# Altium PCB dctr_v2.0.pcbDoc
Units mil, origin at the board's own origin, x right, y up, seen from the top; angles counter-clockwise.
Board outline 7322.83 x 1023.62 mil, 2 copper layers (Top Layer, Bottom Layer); 19 components, 20 nets, 83 pads, 18 vias.
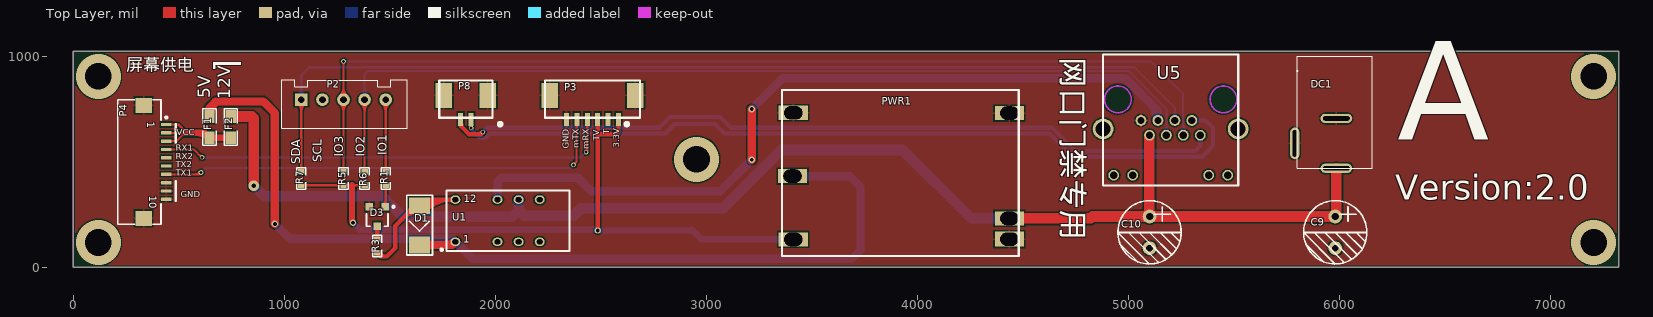
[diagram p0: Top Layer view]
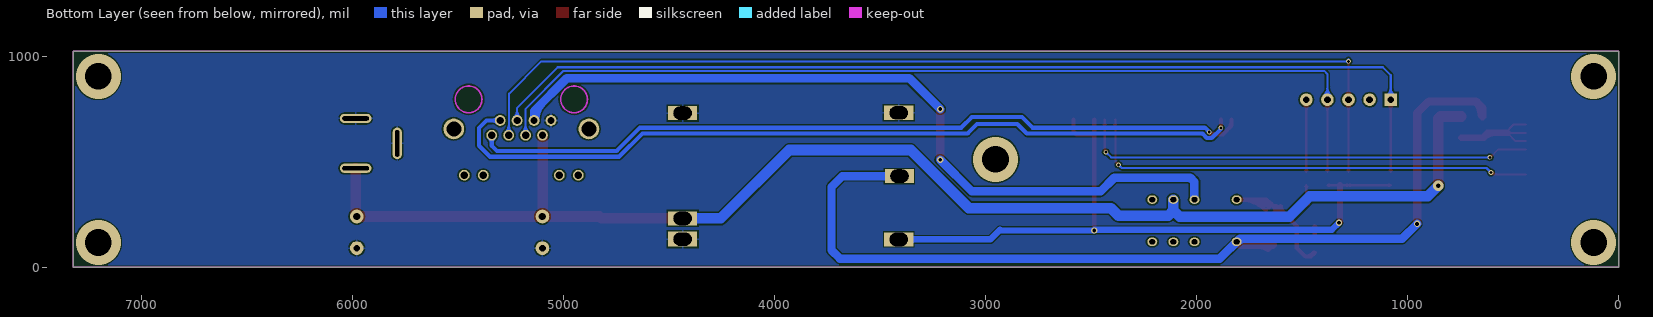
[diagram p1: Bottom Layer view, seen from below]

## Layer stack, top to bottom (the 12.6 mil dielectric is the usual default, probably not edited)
Top Layer: signal copper 1.4
Dielectric: core 12.6, FR-4, Dk 4.8
Bottom Layer: signal copper 1.4

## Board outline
0,0 7322.83,0 7322.83,1023.62 0,1023.62

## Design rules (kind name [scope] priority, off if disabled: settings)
Clearance [All] p1: gap=7
ComponentClearance [All] p1: gap=0 collisioncheckmode=3 verticalgap=0 showdistances=FALSE
HoleSize [All] p1: absolutevalues=TRUE maxlimit=1000 minlimit=1 maxpercent=80.000 minpercent=20.000
HoleToHoleClearance [All] p1: gap=7 allowstackedmicrovias=TRUE
MinimumSolderMaskSliver [All] p1: minsoldermaskwidth=0
PolygonConnect [All] p1: connectstyle=Relief reliefconductorwidth=10 reliefentries=4 polygonreliefangle="90 Angle"
RoomDefinition IO [InComponentClass('IO')] p1: confinementstyle=ConfineIn formatcopy=TRUE lockcomponents=FALSE outline -12707.68,-5560.81 -10707.68,-5560.81 -10707.68,-4560.81 -12707.68,-4560.81
RoutingVias [All] p1: holewidth=14 width=22 viastyle="Through Hole" minholewidth=14 minwidth=22 maxholewidth=280 maxwidth=500
SilkToSilkClearance [All] p1: silktosilkclearance=0
SilkscreenOverComponentPads [All] p1: minsilkscreentomaskgap=0
SolderMaskExpansion [All] p1: expansion=4
TestPointUsage [All] p1: valid=0 allowmultiple=FALSE
Testpoint [All] p1: side=15 testpointundercomponent=TRUE minsize=40 maxsize=100 preferedsize=60 minholesize=0 maxholesize=40 preferedholesize=32 testpointgrid=1 style=1023 order=0-112345678
Width [All] p1: maxlimit=100 minlimit=7 preferedwidth=7
18 further rules are at their usual default settings.

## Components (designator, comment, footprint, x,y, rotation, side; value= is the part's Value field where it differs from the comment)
C9 "220uF" RB.15/.3 5980,241.26 r90 top
C10 "220uF" RB.15/.3 5100,241.26 r90 top
D1 "D-S" DO-214AC(SMA) 1580,341.26 r270 top
D3 "AO3400A" SOT23A 1440,241.26 r180 top
DC1 "DC" DC005 5800,1001.26 r270 top
F1 "FUSE" 0805F 645,665.12 r270 top
F2 "FUSE" 0805F 745,665.12 r270 top
P2 "Header 5" XH2.54-5 1280,794.8 r0 top
P3 "Header 8" FPC/1.25T-6P 2460,701.26 r180 top
P4 "Header 12" FFC/SM1.0-2H10 440,500 r270 top
P8 "Header 4" FPC/1.25T-2P 1860,701.26 r180 top
PWR1 "PWR-1" PWR-1 4480,841.26 r180 top locked
R1 "10K" 0603R 1480,421.26 r90 top
R3 "10K" 0603R 1440,101.26 r90 top
R5 "10K" 0603R 1280,421.26 r270 top
R6 "10K" 0603R 1380,421.26 r270 top
R7 "10K" 0603R 1080,421.26 r270 top
U1 "JDQ(G6S-2)" JDQ-G6S-2 2060,221.26 r0 top
U5 "RJ45-DTE" RJ45-2 5200,661.26 r0 top

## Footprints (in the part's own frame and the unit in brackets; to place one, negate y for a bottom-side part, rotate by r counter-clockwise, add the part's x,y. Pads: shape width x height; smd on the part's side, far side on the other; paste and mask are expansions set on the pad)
0603R [mil]
  rect 25x30 smd: 1(-32,0) 2(32,0)
  silkscreen extent -51,-22 51,22
0805F [mil]
  rect 60x49.21 smd: 1(-50,0) 2(50,0)
  silkscreen extent -87,-31 86,31
DC005 [mm] "9*13.5*10( 外径5.5mm 内径2.1mm)"
  oval 1.1x3.8 hole 0.5 slot 3.2 at 90 deg: 1(13.5,4.7) 2(7.5,4.7)
  oval 3.8x1.1 hole 0.5 slot 3.2 at 0 deg: 3(10.5,-0.3)
  silkscreen extent 0,0 13.5,9
DO-214AC(SMA) [mm]
  rect 2x2.5 smd: A(1.27,1.524) K(5.969,1.524)
  silkscreen extent 0,0 7.19,3.1
FFC/SM1.0-2H10 [mm] "Connector; FH12 Series; 6 Position; 1.0mm Spaced Bottom Eccentric Contact"
  rect 0.4x1.25 smd: 1(-4.5,0) 2(-3.5,0) 3(-2.5,0) 4(-1.5,0) 5(-0.5,0) 6(0.5,0) 7(1.5,0) 8(2.5,0) 9(3.5,0) 10(4.5,0)
  rect 1.8x2 smd: 11(-6.8,-2.725) 12(6.8,-2.725)
  silkscreen extent -7.5,-5.82 7.5,0.13
FPC/1.25T-2P [mm]
  rect 0.6x1.6 smd: 1(-0.625,0) 2(0.625,0)
  rect 2x3 smd: 3(-2.65,-2.9) 4(2.65,-2.9)
  silkscreen extent -4.28,-4.7 3.2,0.71
FPC/1.25T-6P [mm]
  rect 0.6x1.6 smd: 1(-3.125,0) 2(-1.875,0) 3(-0.625,0) 4(0.625,0) 5(1.875,0) 6(3.125,0)
  rect 2x3 smd: 7(-5.15,-2.9) 8(5.15,-2.9)
  silkscreen extent -5.7,-4.7 5.7,0.71
JDQ-G6S-2 [mm] "继电器（G6S-2） 5VDC"
  oval 1.2x1 hole 0.6 slot 0.7 at 0 deg: 1(-6.35,-2.54) 3(-1.27,-2.54) 4(1.27,-2.54) 5(3.81,-2.54) 8(3.81,2.54) 9(1.27,2.54) 10(-1.27,2.54) 12(-6.35,2.54)
  silkscreen extent -8.14,-3.65 7.4,3.65
PWR-1 [mm]
  rect 3.5x1.8 hole 1.6 slot 2.2 at 0 deg: 1(1.125,17.975)
  rect 3.5x1.7 hole 1.6 slot 2.2 at 0 deg: 2(1.125,15.475) 3(1.125,2.8) 4(27.141,2.76) 5(27.225,10.38) 6(27.141,18)
  silkscreen extent 0,0 28.5,20
RB.15/.3 [mil] "8x11x3.5mm"
  round 65 hole 35: 1(0,0)
  round 65 hole 32: 2(-150,0)
  silkscreen extent -225,-150 75,150
RJ45-2 [mm] "FC601-56S-LED"
  round 2.5 hole 1.8: 0(-8.13,-0.13) 0(8.13,-0.13)
  round 1.3 hole 0.89: 1(-3.57,0.89) 2(-2.55,-0.89) 3(-1.53,0.89) 4(-0.51,-0.89) 5(0.51,0.89) 6(1.53,-0.89) 7(2.55,0.89) 8(3.57,-0.89) 9(-6.86,-5.7) 10(-4.57,-5.7) 11(4.57,-5.7) 12(6.86,-5.7)
  Keep-Out Layer circle w0.203: c6.35,3.43 r1.61
  Keep-Out Layer circle w0.203: c-6.35,3.43 r1.61
  silkscreen extent -8.13,-6.92 8.13,8.83
SOT23A [mm] "SOT-23; 3 Leads; Body 3.0 x 2.5 mm, inc. leads (LxW max)"
  rect 0.9x0.95 smd: 1(-0.95,-1.175) 2(0.95,-1.175) 3(0,1.175)
  silkscreen extent -2.07,-1.3 1.3,1.18
XH2.54-5 [mil]
  rect 60x60 hole 32: 1(-200,0)
  round 60 hole 32: 2(-100,0) 3(0,0) 4(100,0) 5(200,0)
  silkscreen extent -292,-136 301,94

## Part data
C9 C10: library part CAP-E, "电解电容"
D1: "肖特基二极管"
D3: library part MOS-N, "NMOS"
DC1: library part DC00X, "圆形电源接口"
F1 F2: "CR-1812-050A60V"
P2: "Header, 5-Pin"
P3: "Header, 8-Pin"
P4: "Header, 12-Pin"
P8: "Header, 4-Pin"
R1 R3 R5 R6 R7: library part RES, "普通电阻"
U1: "继电器（G6S-2 5VDC）"
U5: "设备"

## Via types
v1: diameter 22, hole 14, Top Layer to Bottom Layer, tented both sides, 7 vias
v2: diameter 212.6, hole 125.98, Top Layer to Bottom Layer, 5 vias
v3: diameter 30, hole 18, Top Layer to Bottom Layer, tented both sides, 3 vias
v4: diameter 30, hole 18, Top Layer to Bottom Layer, 2 vias
v5: diameter 50, hole 22, Top Layer to Bottom Layer, tented both sides, 1 vias

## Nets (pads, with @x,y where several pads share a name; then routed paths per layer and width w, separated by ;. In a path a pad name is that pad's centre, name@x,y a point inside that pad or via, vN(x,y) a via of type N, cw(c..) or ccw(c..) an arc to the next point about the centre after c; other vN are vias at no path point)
BTN: P2.3 R5.1 U5.6 | length 5258.9
  Top Layer w10: P2.3@1262.32,777.12 cw(c1219.64,734.44) 1280,734.44 cw(c1340.36,734.44) P2.3@1297.68,777.12 ; P2.3@1262.32,812.48 ccw(c1219.64,855.15) 1280,855.15 ccw(c1340.36,855.15) P2.3@1297.68,812.48 ; P2.3@1269.39,784.19 cw(c1243.79,758.59) 1280,758.59 cw(c1316.21,758.59) P2.3@1290.61,784.19 ; P2.3@1269.39,805.41 ccw(c1243.79,831.01) 1280,831.01 ccw(c1316.21,831.01) P2.3@1290.61,805.41 ; R5.1@1274.7,458.56 ccw(c1261.89,471.37) 1280,471.37 ccw(c1298.11,471.37) R5.1@1285.3,458.56 ; v1@1275.76,972.02 cw(c1265.51,961.77) 1280,961.77 cw(c1294.49,961.77) v1@1284.24,972.02 ; R5.1 P2.3 v1(1280,976.26)
  Bottom Layer w10: v1(1280,976.26) 1280,986.26 1290,976.26 5105,976.26 5257.67,823.59 5257.67,628.79 U5.6 ; v1@1284.24,972.02 cw(c1294.49,961.77) 1294.49,976.26 cw(c1294.49,990.75) v1@1284.24,980.5 ; U5.6@5245.68,640.78 ccw(c5216.72,669.73) 5257.67,669.73 ; 5257.67,657.99 ccw(c5292,657.99) U5.6@5267.72,633.71 ; 5257.67,682.13 ccw(c5316.14,682.13) U5.6@5274.8,640.78
D3V3: P3.1 P3.3 PWR1.6 R5.2 R6.2 R7.2 | length 3464.7
  Top Layer w10: R7.2 R5.2 1320,389.26 R6.2 ; R7.2@1087.8,383.96 cw(c1100.61,371.15) 1100.61,389.26 cw(c1100.61,407.37) R7.2@1087.8,394.56 ; R5.2@1272.2,383.96 ccw(c1259.39,371.15) 1259.39,389.26 ccw(c1259.39,407.37) R5.2@1272.2,394.56 ; R5.2@1287.8,383.96 cw(c1300.61,371.15) 1300.61,389.26 cw(c1300.61,407.37) R5.2@1287.8,394.56 ; R6.2@1372.2,383.96 ccw(c1359.39,371.15) 1359.39,389.26 ccw(c1359.39,407.37) R6.2@1372.2,394.56
  Top Layer w20: v4@2484.61,175.39 2484.61,631.26 ; P3.3 2484.61,631.26 ; P3.1 2583.03,644.29 2570,631.26 2484.61,631.26
  Top Layer w30: v3@1320,216.26 1320,389.26
  Bottom Layer w20: 2928.83,175 2931.47,177.64
  Bottom Layer w30: v3(1325,211.26) 1358.62,177.64 2485,177.64 2487.64,175 2928.83,175 ; 2931.47,177.64 2976.51,132.6 PWR1.6 ; PWR1.6@3362.98,119.54 ccw(c3331.46,88.02) 3331.46,132.6 ccw(c3331.46,177.18) PWR1.6@3362.98,145.65
  other v4: 2485,175
D5V: D1.K F1.1 PWR1.5 U1.1 | length 4814
  Top Layer w40: F1.1 645,756.26 675,786.26 ; F1.1@649.6,720.73 cw(c736.53,724.72) 675,786.26 ; v3(955,206.26) 955,731.26 900,786.26 675,786.26 ; D1.K 1795,106.26 U1.1 ; D1.K@1663.54,92.56 cw(c1696.61,59.5) 1696.61,106.26 cw(c1696.61,153.02) D1.K@1663.54,119.96 ; 1770.61,106.26 ccw(c1770.61,156.71) U1.1@1806.29,121.04
  Bottom Layer w40: v3(955,206.26) 1025.62,135.64 1795.62,135.64 1890,41.26 3690,41.26 3730,81.26 3730,381.26 3678.66,432.6 PWR1.5 ; 1772.11,135.64 cw(c1772.11,87.31) U1.1@1806.29,121.48
D12V: C9.1 C10.1 DC1.1 F2.1 PWR1.2 U1.9 U5.2 | length 6575.5
  Top Layer w50: F2.1 846.14,715.12 855,706.26 v5(855,386.26) ; PWR1.2 4820.75,232.01 4830,241.26 C10.1 C9.1 5985.04,246.3 DC1.1 ; C10.1@5099.61,241.65 U5.2
  Bottom Layer w50: v5(855,386.26) 905,336.26 1463.74,336.26 1560,240 2080,240 2110,270 ; U1.9 2110,270 ; PWR1.2 4254.25,232.01 3930,556.26 3355,556.26 3080,281.26 2406.26,281.26 2370,245 2135,245 2110,270
FEED1: P2.4 R6.1 U5.4 | length 4878.7
  Top Layer w10: P2.4@1362.32,777.12 cw(c1319.64,734.44) 1380,734.44 cw(c1440.36,734.44) P2.4@1397.68,777.12 ; P2.4@1369.39,784.19 cw(c1343.79,758.59) 1380,758.59 cw(c1416.21,758.59) P2.4@1390.61,784.19 ; R6.1@1374.7,458.56 ccw(c1361.89,471.37) 1380,471.37 ccw(c1398.11,471.37) R6.1@1385.3,458.56 ; R6.1 P2.4
  Bottom Layer w10: P2.4@1362.32,812.48 ccw(c1319.64,855.15) 1380,855.15 ccw(c1440.36,855.15) P2.4@1397.68,812.48 ; P2.4@1369.39,805.41 ccw(c1343.79,831.01) 1380,831.01 ccw(c1416.21,831.01) P2.4@1390.61,805.41 ; P2.4 1380,916.26 1395,931.26 5000,931.26 5179.92,751.34 U5.4 ; U5.4@5165.36,640.78 ccw(c5130.21,675.93) 5179.92,675.93 ccw(c5229.63,675.93) U5.4@5194.48,640.78
FEED2: P2.1 R7.1 U5.5 | length 5162.8
  Top Layer w10: P2.1@1062.32,777.12 cw(c1019.64,734.44) 1080,734.44 cw(c1140.36,734.44) P2.1@1097.68,777.12 ; P2.1@1069.39,784.19 cw(c1043.79,758.59) 1080,758.59 cw(c1116.21,758.59) P2.1@1090.61,784.19 ; R7.1@1074.7,458.56 ccw(c1061.89,471.37) 1080,471.37 ccw(c1098.11,471.37) R7.1@1085.3,458.56 ; R7.1 P2.1
  Bottom Layer w10: P2.1@1062.32,812.48 ccw(c1019.64,855.15) 1080,855.15 ccw(c1140.36,855.15) P2.1@1097.68,812.48 ; P2.1@1069.39,805.41 ccw(c1043.79,831.01) 1080,831.01 ccw(c1116.21,831.01) P2.1@1090.61,805.41 ; P2.1 1080,911.26 1117,948.26 5028,948.26 5220.08,756.18 U5.5 ; U5.5@5205.52,710.86 ccw(c5170.37,746.01) 5220.08,746.01 ccw(c5269.79,746.01) U5.5@5234.64,710.86
GND: C9.2 C10.2 D3.2 DC1.2 DC1.3 P3.6 P3.7 P3.8 P4.8 P4.9 P4.10 P4.11 P4.12 P8.3 P8.4 PWR1.1 PWR1.3 PWR1.4 U5.1
IO1: P2.5 R1.2 | length 521.7
  Top Layer w10: P2.5@1462.32,777.12 cw(c1419.64,734.44) 1480,734.44 cw(c1540.36,734.44) P2.5@1497.68,777.12 ; P2.5@1469.39,784.19 cw(c1443.79,758.59) 1480,758.59 cw(c1516.21,758.59) P2.5@1490.61,784.19 ; R1.2@1474.7,458.56 ccw(c1461.89,471.37) 1480,471.37 ccw(c1498.11,471.37) R1.2@1485.3,458.56 ; R1.2 P2.5
LOCK_V+: U1.10 U5.3 | length 3816.2
  Top Layer w40: v4(3215,510) v3(3215,750)
  Bottom Layer w40: U1.10 2010,405 2030,425 2390,425 2455,360 3065,360 v4(3215,510) ; v3(3215,750) 3361.26,896.26 4984.67,896.26 5139.76,741.17 U5.3 ; 5098.49,782.44 cw(c5012.35,696.3) U5.3@5134.17,696.3
NetD1_A: D1.A R3.1 U1.12 | length 1077.1
  Top Layer w20: R3.1 1458,51.26 1485,51.26 ; R3.1@1444.46,70.82 ccw(c1485,103.06) 1485,51.26 ; 1562.68,233.94 cw(c1630.16,166.46) D1.A@1630.16,261.89 ; 1587.2,258.46 ccw(c1554.4,291.26) D1.A@1600.79,291.26 ; D1.A@1596.82,268.08 cw(c1630.16,234.75) D1.A@1630.16,281.89 ; D1.A@1642.33,298.78 cw(c1696.61,244.5) 1696.61,321.26 ; D1.A@1656.47,284.63 cw(c1744.89,196.21) 1744.89,321.26 ; D1.A@1670.61,270.49 cw(c1793.17,147.93) U1.12@1793.17,321.26 ; U1.12@1799.21,314.41 ccw(c1782.68,297.88) 1782.68,321.26 ccw(c1782.68,344.64) U1.12@1799.21,328.11 ; U1.12 1670,321.26 D1.A 1620,291.26 1525,196.26 1525,91.26 1485,51.26
NetD3_1: D3.1 R1.1 | length 175.8
  Top Layer w10: D3.1@1468.41,297.5 ccw(c1440.43,325.48) 1480,325.48 ; R1.1@1474.7,383.96 cw(c1461.89,371.15) 1480,371.15 cw(c1498.11,371.15) R1.1@1485.3,383.96 ; D3.1@1480,290.12 R1.1 ; 1480,312.93 ccw(c1501.83,312.93) D3.1@1486.39,297.5
NetD3_3: D3.3 R3.2 | length 91
  Top Layer w20: D3.3@1434.54,188.56 cw(c1421.37,175.39) 1440,175.39 cw(c1458.63,175.39) D3.3@1445.46,188.56 ; R3.2 D3.3
NetF1_2: F1.2 F2.2 P4.1 P4.2 P4.3 | length 603.9
  Top Layer w10: P4.3 488.43,598.43 525.6,635.6 525.6,637.8 ; P4.2 525.6,637.8 ; P4.1 497.83,677.17 531.4,643.6 ; 537.2,637.8 531.4,643.6 ; 525.6,637.8 531.4,643.6
  Top Layer w30: 525.6,637.8 537.2,637.8 622.33,637.8 F1.2 F2.2 ; 580.09,637.8 cw(c580.09,555.6) F1.2@638.21,613.72
RX1: P3.4 P4.4 | length 2294
  Top Layer w10: P4.4 570.31,559.06 609.06,520.31 v1(610,521.26) ; 596.53,532.84 ccw(c610,546.31) v1@610,527.26 ; 601.09,528.28 cw(c594.08,521.26) v1@604,521.26 ; v1@2425.76,550.5 ccw(c2402.49,573.77) 2435.39,573.77 ; v1(2430,546.26) 2435.39,551.65 P3.4 ; P3.4@2430.58,676.76 cw(c2418.95,665.13) 2435.39,665.13 cw(c2451.84,665.13) P3.4@2440.21,676.76
  Bottom Layer w10: v1(610,521.26) 2405,521.26 v1(2430,546.26) ; v1@614.24,517.02 cw(c624.49,506.77) 624.49,521.26 cw(c624.49,535.75) v1@614.24,525.5 ; v1@2424,546.26 cw(c2409.51,546.26) 2419.76,536.02 cw(c2430,525.77) v1@2430,540.26
RX2: P4.5
SCL: P2.2
SPEAKERA: P8.1 U5.7 | length 3950.6
  Top Layer w20: P8.1 1884.61,661.46 1884.81,661.26 v1(1885,661.26)
  Bottom Layer w20: v1(1885,661.26) 1885,656.66 1928.4,613.26 1951.6,613.26 1968,629.66 1968,631.08 1972.03,635.11 2805.11,635.11 2850,680 3040,680 3084.89,635.11 4626.15,635.11 4737,524.26 5348,524.26 5400,576.26 5400,661.26 5364.96,696.3 U5.7 ; U5.7@5311.42,685.28 cw(c5338.03,658.66) 5338.03,696.3 cw(c5338.03,733.94) U5.7@5311.42,707.32
SPEAKERB: P8.2 U5.8 | length 3822.4
  Top Layer w20: P8.2@1835,700.87 1835,671.65 1875.39,631.26 1930,631.26 v1(1940,641.26) ; P8.2@1837.2,681.57 ccw(c1866.49,681.57) 1845.78,660.87 ; 1913.44,631.26 ccw(c1913.44,667.82) v1@1939.29,641.97
  Bottom Layer w20: v1(1940,641.26) 1960.85,662.11 2777.11,662.11 2827.11,712.11 3065,712.11 3115,662.11 4637.33,662.11 4748.18,551.26 5315,551.26 5340.55,576.81 U5.8 ; U5.8@5329.53,615.2 cw(c5302.91,588.58) 5340.55,588.58 cw(c5378.19,588.58) U5.8@5351.58,615.2
TX1: P3.5 P4.7 | length 2316.9
  Top Layer w10: P4.7 595.94,440.94 v1(605,450) ; 568.65,440.94 ccw(c568.65,486.35) v1@600.76,454.24 ; 592.8,440.94 ccw(c592.8,462.2) v1@607.83,447.17 ; v1(2370,486.26) 2385,501.26 2385,700.08 P3.5 ; v1@2370,492.26 ccw(c2370,506.75) 2380.24,496.5 ccw(c2390.49,486.26) v1@2376,486.26 ; P3.5@2381.36,676.76 cw(c2372.59,667.98) 2385,667.98 ; 2385,662.28 cw(c2405.48,662.28) P3.5@2391,676.76
  Bottom Layer w10: v1(605,450) 626.26,471.26 2355,471.26 v1(2370,486.26) ; v1@605,456 ccw(c605,470.49) 615.24,460.24 ccw(c625.49,450) v1@611,450 ; v1@2364,486.26 cw(c2349.51,486.26) 2359.76,476.02 cw(c2370,465.77) v1@2370,480.26
TX2: P4.6
pads on no net: P3.2 U1.3 U1.4 U1.5 U1.8 U5.0 U5.9 U5.10 U5.11 U5.12
copper on no net:
  other v2: 118.11,118.11 7204.72,118.11 2952.76,511.81 118.11,905.51 7204.72,905.51

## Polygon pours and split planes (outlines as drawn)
GND on Top Layer "Keep-Out Layer-No Net" (solid, remove dead copper): 0,1023.62 0,0 7322.83,0 7322.83,1023.62
GND on Bottom Layer "Keep-Out Layer-No Net" (solid, remove dead copper): 0,0 0,1023.62 7322.83,1023.62 7322.83,0

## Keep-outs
Keep-Out Layer:
  the board outline again, w5

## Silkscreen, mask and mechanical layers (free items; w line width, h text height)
Top Overlay:
  lines w10: 485,315 485,410 ; 485,590 485,680
  text "网口门禁专用" at 4650,995 h180 r270
  text "[" at 645,986.26 h200 r270
  text "屏幕供电" at 250,911.26 h100
  text "5V" at 670,801.26 h100 r90
  text "12V" at 765,796.26 h100 r90
  text "T" at 2550.75,630.65 h50 r90
  text "VCC" at 490,615 h50
  text "TV" at 2502.75,600.25 h50 r90
  text "3.3V" at 2598.21,566.19 h50 r90
  text "mTX" at 2406.75,564.72 h50 r90
  text "GND" at 2358.21,561.35 h50 r90
  text "mRX" at 2454.75,559.74 h50 r90
  text "RX1" at 485,541.26 h50
  text "IO1" at 1498.21,532.07 h70 r90
  text "IO2" at 1395.71,523.87 h70 r90
  text "IO3" at 1293.21,523.46 h70 r90
  text "RX2" at 485,501.45 h50
  text "SCL" at 1190.71,498.94 h70 r90
  text "SDA" at 1088.21,489.72 h70 r90
  text "TX2" at 485,461.65 h50
  text "A" at 6275,450 h800
  text "TX1" at 485,421.84 h50
  text "GND" at 508.86,321.26 h50
  text "Version:2.0" at 6265,280 h200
